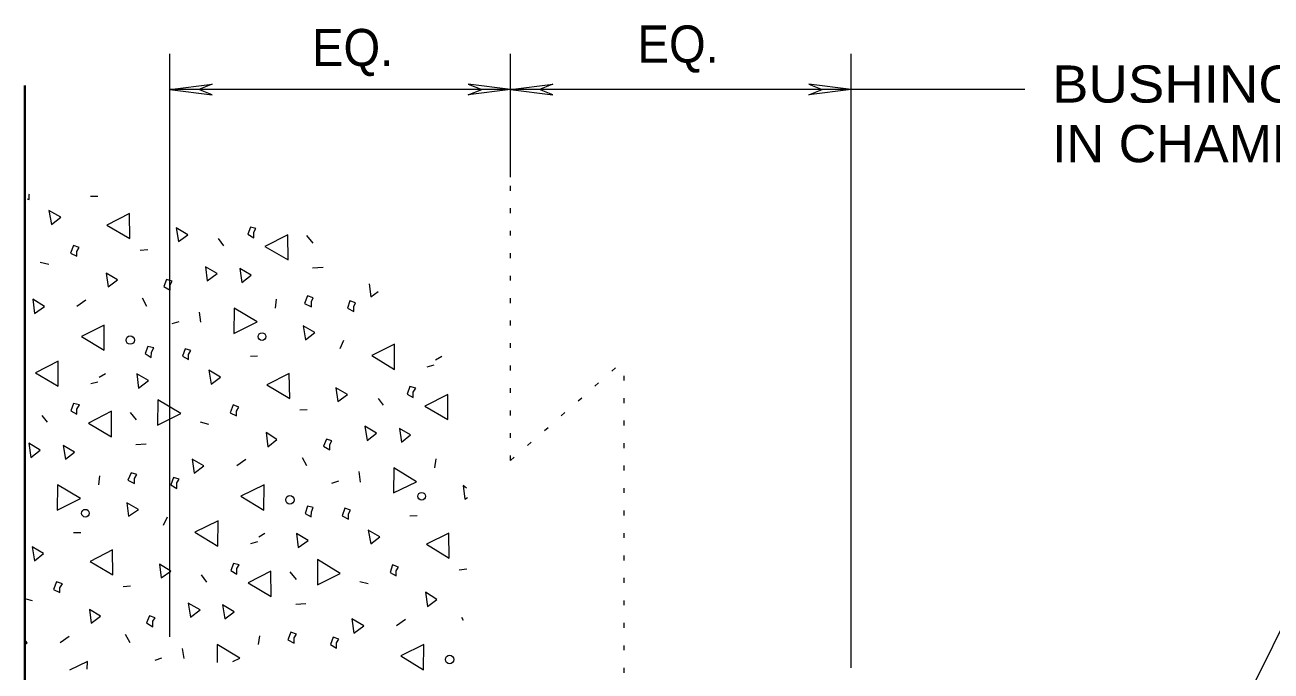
# Model space of a CAD drawing. Extents: x 312583 to 312854, y 144419 to 144597.
# Drawn here: x 312736.16 to 312761.68, y 144466.88 to 144480.11 of the extents above; entities that cross this region are included whole.
import ezdxf

# ---------------------------------------------------------------- set-up
doc = ezdxf.new("R2010")
doc.units = 0
doc.header["$LTSCALE"] = 0.3
doc.linetypes.add('DOTTED', pattern=[1.5, 0.3, -1.2])
doc.layers.add('1', color=7, linetype='Continuous', lineweight=13)

msp = doc.modelspace()

# ---------------------------------------------------------------- linework, layer by layer
at = {"layer": '1'}
for p, q in [((312739.1302, 144467.5845), (312739.1302, 144479.5138)), ((312746.1069, 144476.9915), (312746.1069, 144479.5138)), ((312753.0759, 144466.9481), (312753.0759, 144479.5138)), ((312739.1302, 144478.7855), (312739.9966, 144478.8928)), ((312746.1069, 144478.7855), (312739.1302, 144478.7855)), ((312739.1302, 144478.7855), (312739.9966, 144478.6781)), ((312739.9966, 144478.8928), (312739.7206, 144478.7855)), ((312739.9966, 144478.6781), (312739.7206, 144478.7855)), ((312745.2406, 144478.8928), (312745.5166, 144478.7855)), ((312746.1069, 144478.7855), (312745.2406, 144478.8928)), ((312745.2406, 144478.6781), (312745.5166, 144478.7855)), ((312746.1069, 144478.7855), (312745.2406, 144478.6781)), ((312746.1069, 144478.7855), (312746.9732, 144478.8928)), ((312746.1069, 144478.7855), (312746.9732, 144478.6781)), ((312746.9732, 144478.8928), (312746.6972, 144478.7855)), ((312746.9732, 144478.6781), (312746.6972, 144478.7855)), ((312752.2096, 144478.8928), (312752.4856, 144478.7855)), ((312753.0759, 144478.7855), (312752.2096, 144478.8928)), ((312752.2096, 144478.6781), (312752.4856, 144478.7855)), ((312753.0759, 144478.7855), (312752.2096, 144478.6781)), ((312736.2476, 144476.6388), (312736.2552, 144476.6541)), ((312737.5049, 144476.6005), (312737.6582, 144476.6005)), ((312740.1192, 144475.7341), (312740.2266, 144475.5885)), ((312741.9286, 144475.7955), (312742.0589, 144475.6421)), ((312738.5246, 144475.4965), (312738.6779, 144475.5118)), ((312736.4776, 144475.2511), (312736.6539, 144475.2128)), ((312742.0512, 144475.1361), (312742.2659, 144475.1515)), ((312743.2089, 144474.8065), (312743.2472, 144474.5458)), ((312743.2472, 144474.5458), (312743.3929, 144474.6531)), ((312737.4129, 144474.4768), (312737.2289, 144474.3465)), ((312738.5629, 144474.5228), (312738.6549, 144474.3541)), ((312741.2922, 144474.3081), (312741.3152, 144474.4921)), ((312739.7282, 144474.2315), (312739.7589, 144474.0245)), ((312739.1762, 144473.9938), (312739.3219, 144474.0398)), ((312742.6876, 144473.6488), (312742.6109, 144473.4801)), ((312740.7786, 144473.3268), (312740.9242, 144473.3345)), ((312744.3972, 144473.1121), (312744.5429, 144473.1505)), ((312744.5659, 144473.2501), (312744.6962, 144473.3268)), ((312737.6812, 144472.8975), (312737.8116, 144472.9741)), ((312737.5126, 144472.7671), (312737.6582, 144472.8055)), ((312743.3929, 144472.4605), (312743.5002, 144472.3225)), ((312736.5082, 144472.1155), (312736.6156, 144471.9775)), ((312738.3176, 144472.1768), (312738.4402, 144472.0235)), ((312741.7906, 144472.2305), (312741.9439, 144472.2381)), ((312739.7512, 144471.9851), (312739.9199, 144471.9391)), ((312738.4326, 144471.5175), (312738.6472, 144471.5328)), ((312740.6866, 144471.2108), (312740.5026, 144471.0805)), ((312741.8366, 144471.2568), (312741.9286, 144471.0881)), ((312744.5582, 144471.0421), (312744.5812, 144471.2261)), ((312737.6736, 144470.6971), (312737.6966, 144470.8811)), ((312743.0019, 144470.9655), (312743.0249, 144470.7508)), ((312742.4499, 144470.7278), (312742.5879, 144470.7738)), ((312745.1716, 144470.3981), (312745.2252, 144470.4365)), ((312739.0766, 144470.0301), (312738.9922, 144469.8615)), ((312744.0446, 144470.0608), (312744.1902, 144470.0685)), ((312762.9429, 144469.8845), (312760.7196, 144465.4071)), ((312737.1599, 144469.7158), (312737.3056, 144469.7158)), ((312740.7862, 144469.4935), (312740.9319, 144469.5318)), ((312740.9549, 144469.6315), (312741.0776, 144469.7081)), ((312739.7742, 144468.8495), (312739.8816, 144468.7038)), ((312741.5836, 144468.9108), (312741.7139, 144468.7575)), ((312745.0566, 144468.9568), (312745.2099, 144468.9721)), ((312738.1719, 144468.6118), (312738.3252, 144468.6271)), ((312743.0172, 144468.7191), (312743.1936, 144468.6731)), ((312736.1786, 144468.3588), (312736.3089, 144468.3281)), ((312741.7062, 144468.2515), (312741.9132, 144468.2668)), ((312745.1026, 144467.9831), (312745.1332, 144467.9218)), ((312743.9526, 144467.9371), (312743.7686, 144467.8068)), ((312737.0679, 144467.5921), (312736.8839, 144467.4618)), ((312738.2179, 144467.6381), (312738.3099, 144467.4695)), ((312740.9472, 144467.4235), (312740.9702, 144467.6075)), ((312739.3832, 144467.3468), (312739.4139, 144467.1398)), ((312740.0962, 144467.4235), (312740.0962, 144467.0555)), ((312738.8312, 144467.1091), (312738.9692, 144467.1551))]:
    msp.add_line(p, q, dxfattribs=at)
at = {"layer": '1', "lineweight": 40}
msp.add_line((312736.1632, 144464.9318), (312736.1632, 144478.8698), dxfattribs=at)
at = {"layer": '1', "linetype": 'DOTTED'}
for p, q in [((312746.1069, 144471.1955), (312746.1069, 144476.9915)), ((312746.1069, 144471.1955), (312748.4299, 144473.2425)), ((312748.4299, 144464.0885), (312748.4299, 144473.2425))]:
    msp.add_line(p, q, dxfattribs=at)
at = {"layer": '1'}
for points in [[(312756.6332, 144478.7855), (312753.0759, 144478.7855), (312746.1069, 144478.7855)], [(312736.2092, 144476.5468), (312736.2476, 144476.5315), (312736.2476, 144476.6388)], [(312745.2022, 144470.6281), (312745.1332, 144470.6818), (312745.1716, 144470.3981)], [(312736.1709, 144467.4311), (312736.2092, 144467.4618), (312736.1786, 144467.4925)], [(312740.4182, 144467.0785), (312740.5639, 144467.1475), (312740.0962, 144467.4235)], [(312737.4359, 144466.9251), (312737.4436, 144467.0785), (312737.0756, 144466.9021)]]:
    msp.add_lwpolyline(points, dxfattribs=at)
for points in [[(312736.7076, 144476.0255), (312736.8992, 144476.1711), (312736.6539, 144476.3091)], [(312738.3099, 144475.7341), (312738.3022, 144476.2478), (312737.8422, 144476.0101)], [(312739.3066, 144475.6728), (312739.4982, 144475.8108), (312739.2606, 144475.9565)], [(312740.8476, 144475.8645), (312740.8936, 144475.9411), (312740.7786, 144475.9718), (312740.7249, 144475.8261), (312740.8476, 144475.7495)], [(312741.5529, 144475.2971), (312741.5452, 144475.8108), (312741.0776, 144475.5731)], [(312737.2289, 144475.4735), (312737.2749, 144475.5501), (312737.1599, 144475.5961), (312737.0986, 144475.4351), (312737.2289, 144475.3738)], [(312739.8969, 144474.8678), (312740.0962, 144475.0211), (312739.8586, 144475.1591)], [(312737.8652, 144474.7451), (312738.0569, 144474.8908), (312737.8269, 144475.0288)], [(312739.1379, 144474.7911), (312739.1762, 144474.8601), (312739.0612, 144474.8985), (312739.0076, 144474.7528), (312739.1379, 144474.6761)], [(312740.6022, 144474.8371), (312740.7939, 144474.9828), (312740.5639, 144475.1208)], [(312736.3626, 144474.2008), (312736.5619, 144474.3465), (312736.3242, 144474.4921)], [(312742.0282, 144474.4461), (312742.0666, 144474.5228), (312741.9516, 144474.5611), (312741.8902, 144474.4078), (312742.0282, 144474.3388)], [(312742.8946, 144474.3465), (312742.9329, 144474.4231), (312742.8179, 144474.4615), (312742.7642, 144474.3081), (312742.8946, 144474.2391)], [(312740.4489, 144474.3081), (312740.4412, 144473.7945), (312740.9166, 144474.0321)], [(312737.7886, 144473.4495), (312737.7886, 144473.9631), (312737.3209, 144473.7331)], [(312741.9056, 144473.6641), (312742.0972, 144473.8098), (312741.8596, 144473.9478)], [(312738.7546, 144473.4111), (312738.8006, 144473.4955), (312738.6779, 144473.5261), (312738.6242, 144473.3805), (312738.7469, 144473.3038)], [(312739.5136, 144473.3651), (312739.5596, 144473.4418), (312739.4446, 144473.4801), (312739.3909, 144473.3268), (312739.5136, 144473.2578)], [(312743.7302, 144473.0585), (312743.7302, 144473.5721), (312743.2626, 144473.3421)], [(312736.8456, 144472.7135), (312736.8456, 144473.2271), (312736.3779, 144472.9895)], [(312738.4862, 144472.6751), (312738.6932, 144472.8285), (312738.4556, 144472.9665)], [(312739.9736, 144472.7518), (312740.1652, 144472.8975), (312739.9276, 144473.0431)], [(312741.5836, 144472.4605), (312741.5759, 144472.9741), (312741.1159, 144472.7441)], [(312742.5726, 144472.3991), (312742.7642, 144472.5448), (312742.5266, 144472.6828)], [(312744.1136, 144472.5908), (312744.1672, 144472.6751), (312744.0446, 144472.7058), (312743.9909, 144472.5525), (312744.1136, 144472.4835)], [(312737.2289, 144472.2458), (312737.2826, 144472.3301), (312737.1599, 144472.3608), (312737.1062, 144472.2075), (312737.2289, 144472.1385)], [(312738.8849, 144472.4375), (312738.8772, 144471.9161), (312739.3526, 144472.1538)], [(312740.4949, 144472.1998), (312740.5409, 144472.2841), (312740.4259, 144472.3301), (312740.3646, 144472.1691), (312740.4949, 144472.1078)], [(312744.8189, 144472.0311), (312744.8189, 144472.5448), (312744.3512, 144472.3071)], [(312737.9342, 144471.6785), (312737.9342, 144472.1998), (312737.4666, 144471.9545)], [(312743.1706, 144471.6018), (312743.3622, 144471.7551), (312743.1246, 144471.8931)], [(312743.8759, 144471.5711), (312744.0599, 144471.7168), (312743.8299, 144471.8471)], [(312741.1389, 144471.4715), (312741.3229, 144471.6248), (312741.1006, 144471.7628)], [(312742.4039, 144471.5175), (312742.4499, 144471.5941), (312742.3349, 144471.6325), (312742.2736, 144471.4868), (312742.4039, 144471.4101)], [(312736.2859, 144471.2568), (312736.4776, 144471.4025), (312736.2399, 144471.5481)], [(312736.9912, 144471.2185), (312737.1752, 144471.3641), (312736.9452, 144471.5021)], [(312739.6286, 144470.9348), (312739.8279, 144471.0805), (312739.5902, 144471.2185)], [(312738.4096, 144470.8275), (312738.4556, 144470.9041), (312738.3406, 144470.9425), (312738.2716, 144470.7891), (312738.4096, 144470.7201)], [(312739.2759, 144470.7355), (312739.3219, 144470.8121), (312739.2069, 144470.8428), (312739.1532, 144470.6971), (312739.2759, 144470.6205)], [(312743.7149, 144471.0421), (312743.7072, 144470.5285), (312744.1826, 144470.7585)], [(312736.8302, 144470.6971), (312736.8226, 144470.1758), (312737.2979, 144470.4135)], [(312741.0546, 144470.1758), (312741.0622, 144470.6971), (312740.5869, 144470.4595)], [(312738.2869, 144470.0531), (312738.4862, 144470.1911), (312738.2486, 144470.3291)], [(312742.0282, 144470.1451), (312742.0666, 144470.2295), (312741.9516, 144470.2601), (312741.8979, 144470.1068), (312742.0206, 144470.0378)], [(312742.7872, 144470.0991), (312742.8256, 144470.1758), (312742.7106, 144470.2141), (312742.6569, 144470.0608), (312742.7872, 144469.9918)], [(312740.1116, 144469.4398), (312740.1192, 144469.9611), (312739.6439, 144469.7235)], [(312743.2472, 144469.4858), (312743.4312, 144469.6315), (312743.1936, 144469.7695)], [(312741.7599, 144469.4091), (312741.9592, 144469.5548), (312741.7216, 144469.7005)], [(312744.8496, 144469.1945), (312744.8419, 144469.7081), (312744.3819, 144469.4781)], [(312736.3626, 144469.1408), (312736.5466, 144469.2865), (312736.3089, 144469.4245)], [(312737.9649, 144468.8495), (312737.9572, 144469.3631), (312737.4972, 144469.1255)], [(312738.9539, 144468.7881), (312739.1532, 144468.9261), (312738.9156, 144469.0718)], [(312740.5026, 144468.9798), (312740.5486, 144469.0565), (312740.4336, 144469.0871), (312740.3799, 144468.9415), (312740.5026, 144468.8648)], [(312742.1509, 144469.1638), (312742.1509, 144468.6501), (312742.6186, 144468.8801)], [(312743.7609, 144468.9338), (312743.8146, 144469.0105), (312743.6919, 144469.0565), (312743.6382, 144468.9031), (312743.7609, 144468.8341)], [(312741.2079, 144468.4125), (312741.2002, 144468.9261), (312740.7326, 144468.6885)], [(312736.8762, 144468.5888), (312736.9299, 144468.6655), (312736.8072, 144468.7115), (312736.7459, 144468.5505), (312736.8762, 144468.4891)], [(312744.4049, 144468.2055), (312744.5966, 144468.3511), (312744.3666, 144468.4968)], [(312739.5519, 144467.9831), (312739.7512, 144468.1365), (312739.5059, 144468.2745)], [(312737.5202, 144467.8605), (312737.7119, 144468.0061), (312737.4819, 144468.1441)], [(312738.7852, 144467.9065), (312738.8312, 144467.9755), (312738.7162, 144468.0138), (312738.6549, 144467.8681), (312738.7852, 144467.7915)], [(312740.2572, 144467.9525), (312740.4489, 144468.0981), (312740.2112, 144468.2361)], [(312742.8946, 144467.6611), (312743.1016, 144467.8068), (312742.8562, 144467.9525)], [(312741.6756, 144467.5615), (312741.7216, 144467.6381), (312741.6066, 144467.6765), (312741.5452, 144467.5231), (312741.6756, 144467.4541)], [(312742.5419, 144467.4618), (312742.5879, 144467.5385), (312742.4729, 144467.5768), (312742.4192, 144467.4235), (312742.5419, 144467.3545)], [(312744.3206, 144466.9098), (312744.3282, 144467.4235), (312743.8606, 144467.1935)]]:
    msp.add_lwpolyline(points, close=True, dxfattribs=at)
for centre, radius in [((312738.3207, 144473.6575), 0.0865), ((312741.017, 144473.7303), 0.0783), ((312744.286, 144470.4613), 0.0783), ((312741.5896, 144470.3886), 0.0865), ((312737.4011, 144470.1144), 0.0783), ((312744.8586, 144467.1196), 0.0865)]:
    msp.add_circle(centre, radius, dxfattribs=at)

# ---------------------------------------------------------------- texts
for s, width, p in [('EQ.', 0.95, (312742.0411, 144479.2656)), ('EQ.', 0.95, (312748.7056, 144479.3366)), ('BUSHING TO BE CENTERED', 1.1, (312757.191, 144478.5182)), ('IN CHAMBER', 1.05, (312757.191, 144477.2982))]:
    msp.add_text(s, height=0.76, dxfattribs=dict(at, width=width)).set_placement(p)

doc.saveas('drawing.dxf')
